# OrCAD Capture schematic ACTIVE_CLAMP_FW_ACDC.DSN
size A
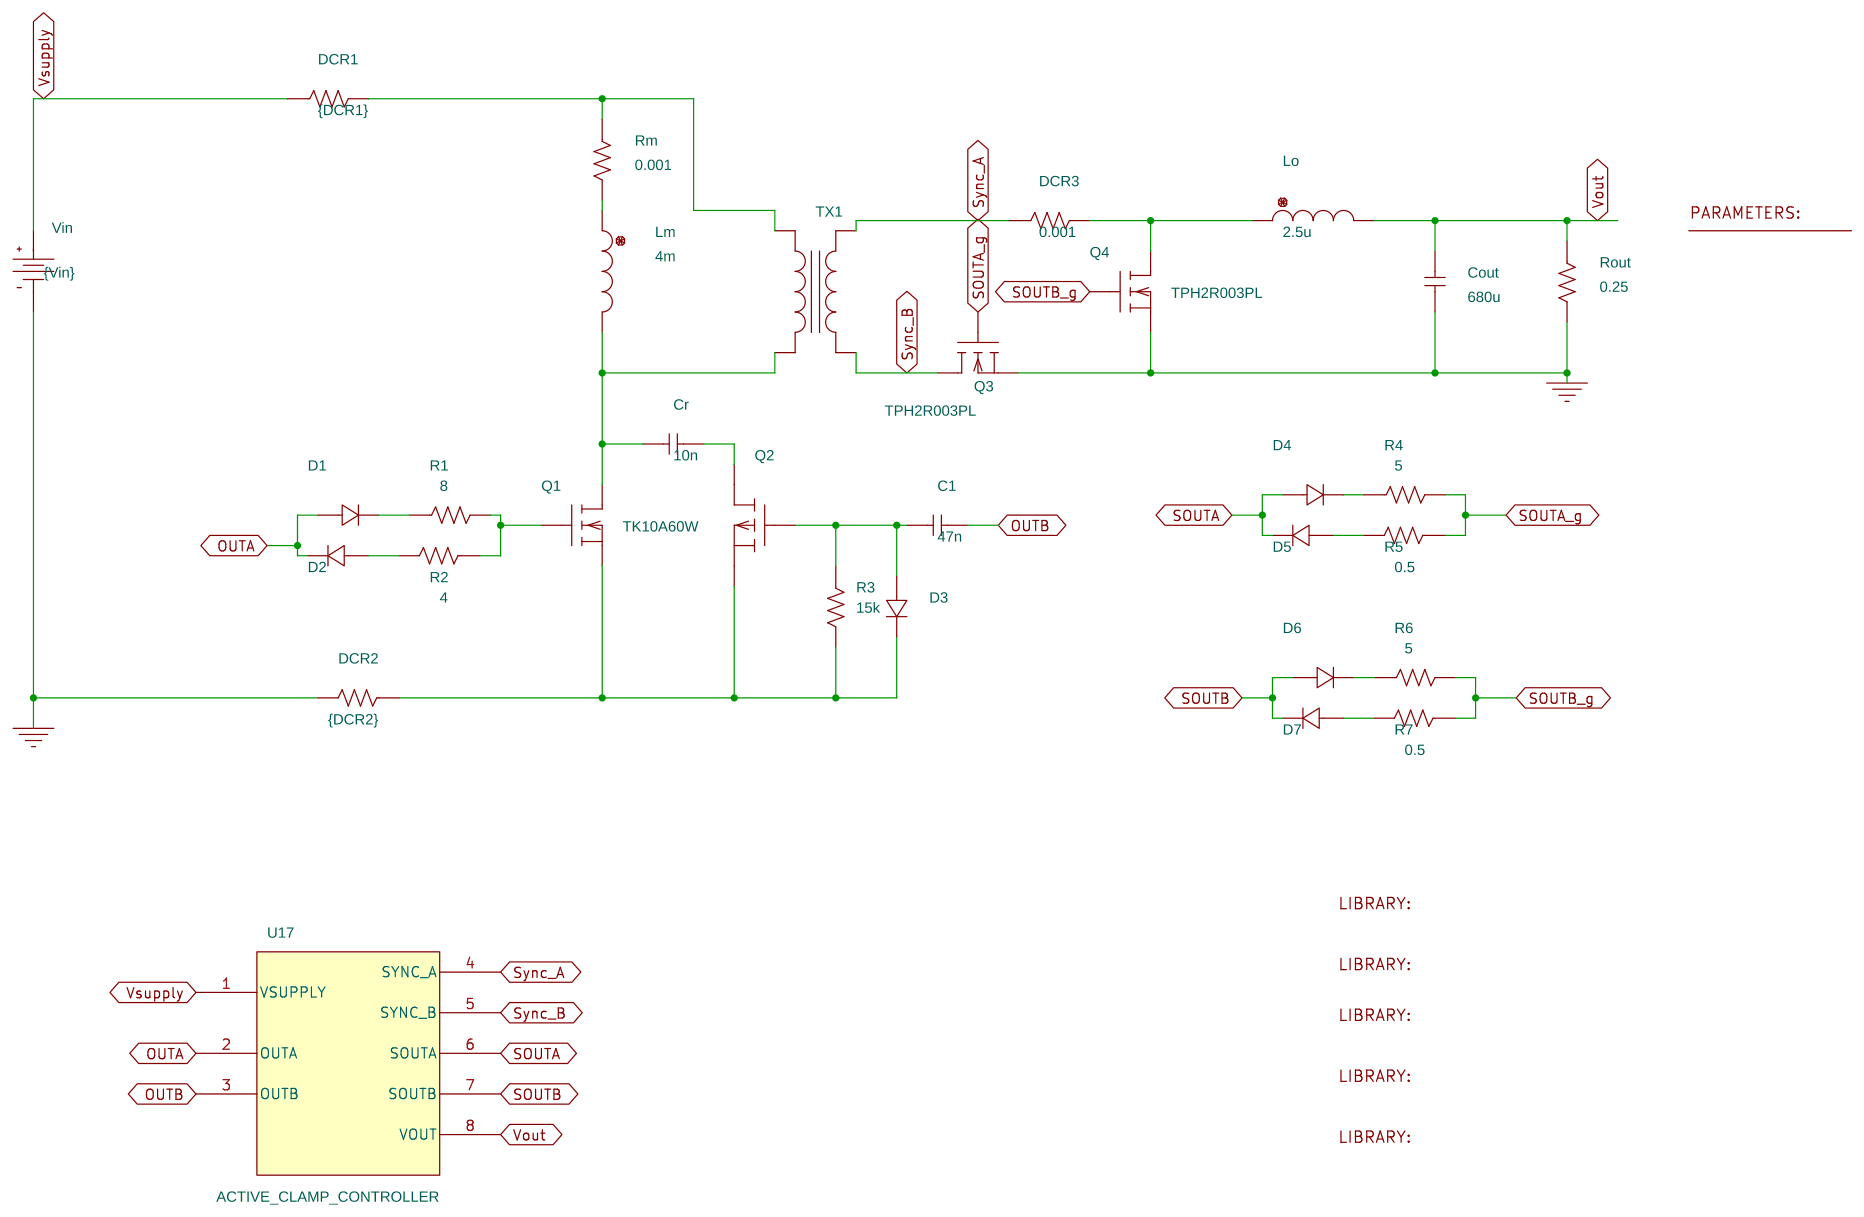
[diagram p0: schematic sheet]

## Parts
1  PARAM
C1  47n  [cap196]
Cout  680u  [cap196]
Cr  10n  [cap196]
D1  Diode_nom
D2  Diode_nom
D3  Diode_nom
D4  Diode_nom
D5  Diode_nom
D6  Diode_nom
D7  Diode_nom
DCR1  {DCR1}  [AXRC05]
DCR2  {DCR2}  [AXRC05]
DCR3  0.001  [AXRC05]
LIB2  LIB
LIB3  LIB
LIB5  LIB
LIB6  LIB
LIB7  LIB
Lm  4m  [DISC350x175LS200x100034]
Lo  2.5u  [DISC350x175LS200x100034]
Q1  TK10A60W
Q2  power_pmos
Q3  TPH2R003PL
Q4  TPH2R003PL
R1  8  [AXRC05]
R2  4  [AXRC05]
R3  15k  [AXRC05]
R4  5  [AXRC05]
R5  0.5  [AXRC05]
R6  5  [AXRC05]
R7  0.5  [AXRC05]
Rm  0.001  [AXRC05]
Rout  0.25  [AXRC05]
TX1  XFRM_NONLINEAR
U17  ACTIVE_CLAMP_CONTROLLER
Vin  VDC

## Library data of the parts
1 = PARAM: DCR1: 5m; DCR2: 5m; Fc: 150k; Td: 370n; Vdrv_H_p: 12; Vdrv_H_r: 12; Vdrv_H_s: 12; Vin: 200; Vout: 5
C1 Cout Cr = C
D1-D7 = Diode_nom
DCR1-DCR3 R1-R7 Rm Rout = R
LIB2 = LIB: FILENAME: ../../../lib/TPH2R003PL_PSpice_20180808.lib
LIB3 = LIB: FILENAME: ../../../lib/diode_nom.lib
LIB5 = LIB: FILENAME: ../../../lib/TK10A60W_PSpice_20130516.lib
LIB6 = LIB: FILENAME: ../../../lib/power_pmos.lib
LIB7 = LIB: FILENAME: ../../../lib/Active_Clamp_Controller.lib
Lm Lo = L
Q1 = TK10A60W
Q2 = power_pmos
Q3 Q4 = TPH2R003PL
TX1 = XFRM_NONLINEAR: COUPLING: 1; L1_TURNS: 50; L2_TURNS: 5
U17 = ACTIVE_CLAMP_CONTROLLER
Vin = VDC: DC: {Vin}

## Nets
0: Cout.2 DCR2.2 Q3.0(s) Q4.0(s) Rout.2 Vin.1(-)
OUTA: D1.0(1) D2.1(2) U17.2(OUTA)
OUTB: C1.2 U17.3(OUTB)
SOUTA: D4.0(1) D5.1(2) U17.6(SOUTA)
SOUTA_g: Q3.1(g) R4.2 R5.1
SOUTB: D6.0(1) D7.1(2) U17.7(SOUTB)
SOUTB_g: Q4.1(g) R6.2 R7.1
Sync_A: DCR3.1 TX1.2(3) U17.4(SYNC_A)
Sync_B: Q3.2(d) TX1.3(4) U17.5(SYNC_B)
Vout: Cout.1 Lo.2 Rout.1 U17.8(VOUT)
Vsupply: DCR1.1 U17.1(VSUPPLY) Vin.0(+)
N16192470: DCR1.2 Rm.1 TX1.0(1)
N16192518: Lm.1 Rm.2
N16192654: DCR3.2 Lo.1 Q4.2(d)
N16192764: Cr.1 Lm.2 Q1.2(d) TX1.1(2)
N16192874: Cr.2 Q2.2(d)
N16192982: D4.1(2) R4.1
N16193012: D1.1(2) R1.1
N16193016: Q1.1(g) R1.2 R2.1
N16193182: C1.1 D3.0(1) Q2.0(g) R3.1
N16193218: D5.0(1) R5.2
N16193246: D2.0(1) R2.2
N16193258: D3.1(2) DCR2.1 Q1.0(s) Q2.1(s) R3.2
N16193368: D6.1(2) R6.1
N16193482: D7.0(1) R7.2
